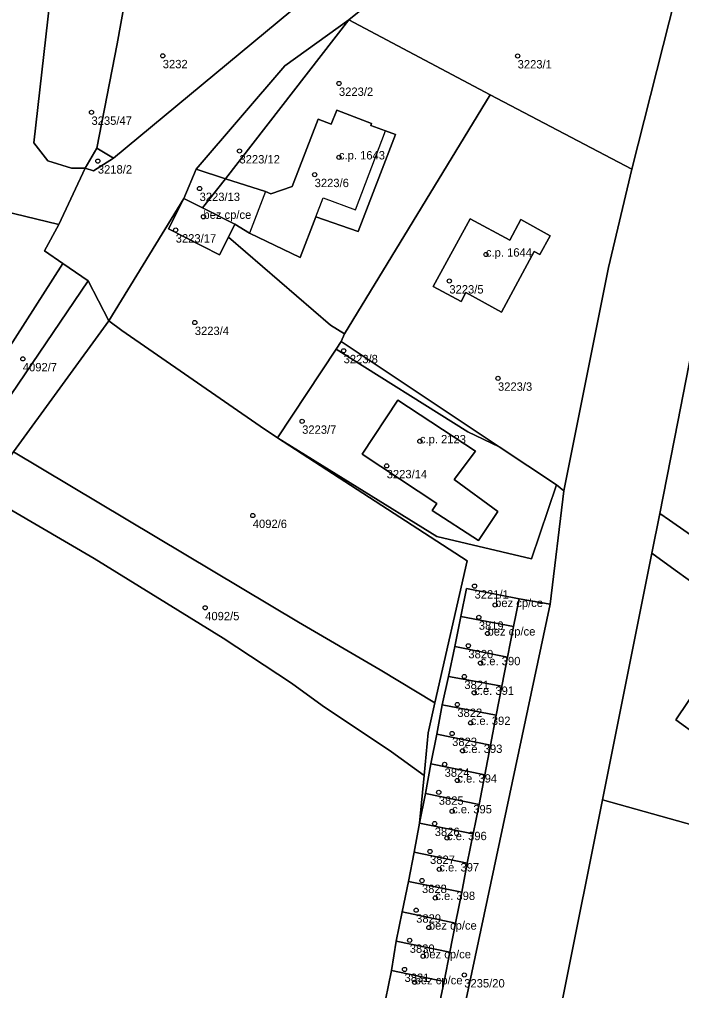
# Model space of a CAD drawing. Extents: x -878211 to -870363, y -1058464 to -1052522.
# Drawn here: x -875140.3 to -875061.1, y -1056719.1 to -1056603.1 of the extents above; entities that cross this region are included whole.
import ezdxf

# ---------------------------------------------------------------- set-up
doc = ezdxf.new("R2010")
doc.units = 0
for name, color, linetype in [('Vrstva 50', 7, 'Continuous'), ('Vrstva 51', 7, 'Continuous'), ('Vrstva 52', 7, 'Continuous')]:
    doc.layers.add(name, color=color, linetype=linetype)

msp = doc.modelspace()

# ---------------------------------------------------------------- linework, layer by layer
at = {"layer": 'Vrstva 50'}
for centre in [(-875123.14, -1056607.45994), (-875080.72, -1056607.47994), (-875102.08, -1056610.75994), (-875131.66, -1056614.21994), (-875113.97, -1056618.82994), (-875130.9, -1056620.03994), (-875102.08, -1056619.58994), (-875104.98, -1056621.65994), (-875118.74, -1056623.31994), (-875118.28, -1056626.68994), (-875121.59, -1056628.27994), (-875084.51, -1056631.19994), (-875088.88, -1056634.36994), (-875119.31, -1056639.32994), (-875101.52, -1056642.69994), (-875139.87, -1056643.66994), (-875083.07, -1056645.98994), (-875106.48, -1056651.12994), (-875092.4, -1056653.50994), (-875096.37, -1056656.44994), (-875112.38, -1056662.38994), (-875085.87, -1056670.81994), (-875118.07, -1056673.40994), (-875083.41, -1056673.06994), (-875085.36, -1056674.53994), (-875084.32, -1056676.47994), (-875086.61, -1056677.94994), (-875085.15, -1056680.01994), (-875087.09, -1056681.61994), (-875085.91, -1056683.55994), (-875087.93, -1056684.95994), (-875086.33, -1056687.15994), (-875088.55, -1056688.42994), (-875087.3, -1056690.49994), (-875089.45, -1056692.10994), (-875087.93, -1056694.03994), (-875090.15, -1056695.44994), (-875088.55, -1056697.71994), (-875090.63, -1056699.18994), (-875089.17, -1056700.91994), (-875091.19, -1056702.51994), (-875090.08, -1056704.65994), (-875092.16, -1056705.99994), (-875090.56, -1056708.06994), (-875092.85, -1056709.53994), (-875091.33, -1056711.60994), (-875093.62, -1056713.13994), (-875092.02, -1056715.03994), (-875094.24, -1056716.61994), (-875087.1, -1056717.27994), (-875093.03, -1056718.14994)]:
    msp.add_circle(centre, 0.25, dxfattribs=at)
at = {"layer": 'Vrstva 51'}
for points in [[(-874975.13, -1056393.67), (-874980.45, -1056410.63), (-874983.57, -1056424.89), (-875001.65, -1056483.66), (-875005.15, -1056492.08), (-875032.55, -1056540.02), (-875035.19, -1056534.63), (-875039.79, -1056543.8), (-875051.68, -1056572.91), (-875052.45, -1056574.91), (-875061.84, -1056600.38), (-875067.07, -1056621.01), (-875069.87, -1056632.77), (-875075.2, -1056659.42), (-875076.83, -1056672.97), (-875088.05, -1056725.8)], [(-875147.44, -1056651.53), (-875135.09, -1056632.27), (-875137.28, -1056630.77), (-875135.57, -1056627.63), (-875150.54, -1056623.98)], [(-875079.85, -1056742.65), (-875070.58, -1056696.36), (-875064.69, -1056666.87), (-875063.74, -1056662.13), (-875061.56, -1056651.21), (-875058, -1056632.84)], [(-875096.5, -1056720.24), (-875095.8, -1056716.75), (-875095.25, -1056713.24), (-875094.52, -1056709.74), (-875093.77, -1056706.12), (-875093.1, -1056702.61), (-875092.44, -1056699.14), (-875091.91, -1056693.44), (-875095.8, -1056690.63), (-875104.09, -1056685.1), (-875107.77, -1056682.42), (-875115.91, -1056677.03), (-875131.33, -1056667.53), (-875144.62, -1056659.79)], [(-875052, -1056670.3), (-875062.58, -1056662.94), (-875063.74, -1056662.13), (-875064.69, -1056666.87), (-875061.87, -1056668.91), (-875054.13, -1056674.49)], [(-875088.05, -1056725.8), (-875076.83, -1056672.97), (-875080.52, -1056672.32), (-875081.22, -1056675.66), (-875081.93, -1056679.3), (-875082.61, -1056682.78), (-875083.27, -1056686.24), (-875083.97, -1056689.81), (-875084.65, -1056693.35), (-875085.31, -1056696.89), (-875086.03, -1056700.41), (-875086.74, -1056703.92), (-875087.41, -1056707.4), (-875088.16, -1056711.08), (-875088.82, -1056714.54), (-875089.5, -1056718.06), (-875090.24, -1056721.62)]]:
    msp.add_lwpolyline(points, dxfattribs=at)
for points in [[(-875132.07, -1056634.34), (-875129.58, -1056639.14), (-875120.62, -1056624.51), (-875119.16, -1056621.01), (-875108.56, -1056608.67), (-875100.9, -1056603.18), (-875092.92, -1056596.72), (-875079.96, -1056589.72), (-875078.48, -1056587.09), (-875068.77, -1056576.4), (-875069.25, -1056570.23), (-875083.66, -1056582.09), (-875092.7, -1056589.53), (-875129.03, -1056619.67), (-875131.42, -1056621.2), (-875132.43, -1056620.89), (-875135.57, -1056627.63), (-875137.28, -1056630.77), (-875135.09, -1056632.27)], [(-875092.7, -1056589.53), (-875105.74, -1056586.1), (-875107.74, -1056599.08), (-875118.83, -1056597.36), (-875117.58, -1056589.47), (-875125.11, -1056588.01), (-875127.7, -1056601.16), (-875128.61, -1056606.02), (-875131.01, -1056618.5), (-875129.03, -1056619.67)], [(-875092.92, -1056596.72), (-875100.9, -1056603.18), (-875084.01, -1056612.14), (-875067.07, -1056621.01), (-875061.84, -1056600.38), (-875072.18, -1056596.84), (-875070.92, -1056593.21), (-875074.27, -1056592.01), (-875079.61, -1056589.86), (-875079.96, -1056589.72)], [(-875136.63, -1056600.96), (-875236.32, -1056602.29), (-875236.35, -1056608.98), (-875235.7, -1056613.74), (-875221.55, -1056617.25), (-875208.62, -1056621), (-875196.21, -1056625.52), (-875183.08, -1056631.34), (-875173.25, -1056636.71), (-875161.79, -1056643.58), (-875150.54, -1056623.98), (-875135.57, -1056627.63), (-875132.43, -1056620.89), (-875134.07, -1056620.89), (-875136.87, -1056620), (-875138.55, -1056617.84)], [(-875138.55, -1056617.84), (-875136.87, -1056620), (-875134.07, -1056620.89), (-875132.43, -1056620.89), (-875131.01, -1056618.5), (-875128.61, -1056606.02), (-875127.7, -1056601.16), (-875136.63, -1056600.96)], [(-875115.66, -1056622.14), (-875100.9, -1056603.18), (-875108.56, -1056608.67), (-875119.16, -1056621.01)], [(-875114.51, -1056627.56), (-875115.29, -1056629.12), (-875103.09, -1056639.66), (-875101.43, -1056640.66), (-875084.01, -1056612.14), (-875100.9, -1056603.18), (-875115.66, -1056622.14), (-875110.84, -1056623.69), (-875110.23, -1056623.95), (-875107.67, -1056623.06), (-875104.57, -1056615.01), (-875103.02, -1056615.62), (-875102.34, -1056613.94), (-875098.17, -1056615.55), (-875098.25, -1056615.79), (-875096.51, -1056616.44), (-875095.33, -1056616.86), (-875099.8, -1056628.45), (-875104.85, -1056626.68), (-875106.72, -1056631.55), (-875112.76, -1056628.63)], [(-875076.07, -1056658.7), (-875075.2, -1056659.42), (-875069.87, -1056632.77), (-875067.07, -1056621.01), (-875084.01, -1056612.14), (-875101.43, -1056640.66), (-875101.81, -1056641.6), (-875082.94, -1056654.17)], [(-875118.38, -1056625.63), (-875114.51, -1056627.56), (-875112.76, -1056628.63), (-875106.72, -1056631.55), (-875104.85, -1056626.68), (-875099.8, -1056628.45), (-875095.33, -1056616.86), (-875096.51, -1056616.44), (-875098.25, -1056615.79), (-875098.17, -1056615.55), (-875102.34, -1056613.94), (-875103.02, -1056615.62), (-875104.57, -1056615.01), (-875107.67, -1056623.06), (-875110.23, -1056623.95), (-875110.84, -1056623.69), (-875115.66, -1056622.14)], [(-875132.43, -1056620.89), (-875131.42, -1056621.2), (-875129.03, -1056619.67), (-875131.01, -1056618.5)], [(-875120.62, -1056624.51), (-875118.38, -1056625.63), (-875115.66, -1056622.14), (-875119.16, -1056621.01)], [(-875128.02, -1056640.29), (-875111.51, -1056651.71), (-875109.41, -1056653.11), (-875102.41, -1056642.51), (-875101.81, -1056641.6), (-875101.43, -1056640.66), (-875103.09, -1056639.66), (-875115.29, -1056629.12), (-875116.34, -1056631.22), (-875122.46, -1056628.14), (-875120.62, -1056624.51), (-875129.58, -1056639.14)], [(-875120.62, -1056624.51), (-875122.46, -1056628.14), (-875116.34, -1056631.22), (-875115.29, -1056629.12), (-875114.51, -1056627.56), (-875118.38, -1056625.63)], [(-875087.48, -1056636.81), (-875086.9, -1056635.74), (-875082.66, -1056638.07), (-875078.75, -1056630.82), (-875078.05, -1056631.2), (-875076.84, -1056628.96), (-875080.32, -1056627.03), (-875081.64, -1056629.5), (-875086.4, -1056626.95), (-875090.81, -1056635.01)], [(-875087.48, -1056636.81), (-875090.81, -1056635.01), (-875086.4, -1056626.95), (-875081.64, -1056629.5), (-875080.32, -1056627.03), (-875076.84, -1056628.96), (-875078.05, -1056631.2), (-875078.75, -1056630.82), (-875082.66, -1056638.07), (-875086.9, -1056635.74)], [(-875147.44, -1056651.53), (-875144.63, -1056652.87), (-875132.07, -1056634.34), (-875135.09, -1056632.27)], [(-875054.2, -1056635.62), (-875058, -1056632.84), (-875061.56, -1056651.21), (-875063.74, -1056662.13), (-875062.58, -1056662.94), (-875052, -1056670.3), (-875031.7, -1056677.75), (-874994.36, -1056690.62), (-874969.93, -1056695.59), (-874964.18, -1056690.59), (-874960.32, -1056681.28), (-874969.59, -1056675.5), (-874970.83, -1056674.71), (-874976.58, -1056671.11), (-874979.49, -1056669.39), (-874981.46, -1056668.14), (-875047.89, -1056640.23)], [(-875158.29, -1056678.56), (-875144.62, -1056659.79), (-875140.97, -1056654.78), (-875129.58, -1056639.14), (-875132.07, -1056634.34), (-875144.63, -1056652.87), (-875148.03, -1056657.88), (-875152.95, -1056665.14)], [(-875090.61, -1056684.77), (-875086.74, -1056667.79), (-875109.41, -1056653.11), (-875111.51, -1056651.71), (-875128.02, -1056640.29), (-875129.58, -1056639.14), (-875140.97, -1056654.78), (-875106.91, -1056675.12), (-875097.17, -1056680.82)], [(-875082.94, -1056654.17), (-875101.81, -1056641.6), (-875102.41, -1056642.51), (-875086.67, -1056652.4)], [(-875086.67, -1056652.4), (-875102.41, -1056642.51), (-875109.41, -1056653.11), (-875090.39, -1056664.91), (-875079.06, -1056667.56), (-875076.07, -1056658.7), (-875082.94, -1056654.17)], [(-875090.93, -1056661.77), (-875085.38, -1056665.36), (-875083.1, -1056661.9), (-875088.29, -1056658.09), (-875085.76, -1056654.68), (-875095.06, -1056648.6), (-875099.29, -1056655.07), (-875090.38, -1056660.94)], [(-875090.93, -1056661.77), (-875090.38, -1056660.94), (-875099.29, -1056655.07), (-875095.06, -1056648.6), (-875085.76, -1056654.68), (-875088.29, -1056658.09), (-875083.1, -1056661.9), (-875085.38, -1056665.36)], [(-875091.91, -1056693.44), (-875092.44, -1056699.14), (-875091.75, -1056695.59), (-875091.11, -1056692.06), (-875090.36, -1056688.49), (-875089.73, -1056685.01), (-875088.99, -1056681.62), (-875088.24, -1056678.03), (-875087.51, -1056674.45), (-875086.83, -1056671.12), (-875080.52, -1056672.32), (-875076.83, -1056672.97), (-875075.2, -1056659.42), (-875076.07, -1056658.7), (-875079.06, -1056667.56), (-875090.39, -1056664.91), (-875109.41, -1056653.11), (-875086.74, -1056667.79), (-875090.61, -1056684.77), (-875091.43, -1056688.36)], [(-875090.61, -1056684.77), (-875097.17, -1056680.82), (-875106.91, -1056675.12), (-875140.97, -1056654.78), (-875144.62, -1056659.79), (-875131.33, -1056667.53), (-875115.91, -1056677.03), (-875107.77, -1056682.42), (-875104.09, -1056685.1), (-875095.8, -1056690.63), (-875091.91, -1056693.44), (-875091.43, -1056688.36)], [(-875033.98, -1056681.51), (-875054.13, -1056674.49), (-875061.87, -1056668.91), (-875064.69, -1056666.87), (-875070.58, -1056696.36), (-874971.25, -1056724.17), (-874965.51, -1056725.78), (-874958.57, -1056727.67), (-874952.5, -1056725.13), (-874945.84, -1056719.49), (-874939.85, -1056712.99), (-874937.64, -1056707.11), (-874938.78, -1056706.6), (-874939.54, -1056709.59), (-874960.23, -1056695.82), (-874961.04, -1056695.28), (-874963.53, -1056701.5), (-874995.69, -1056695.3)], [(-875081.22, -1056675.66), (-875080.52, -1056672.32), (-875086.83, -1056671.12), (-875087.51, -1056674.45)], [(-875088.24, -1056678.03), (-875081.93, -1056679.3), (-875081.22, -1056675.66), (-875087.51, -1056674.45)], [(-875082.61, -1056682.78), (-875081.93, -1056679.3), (-875088.24, -1056678.03), (-875088.99, -1056681.62)], [(-875039.56, -1056689.55), (-875045.19, -1056698.06), (-875048.14, -1056696.15), (-875048.31, -1056696.37), (-875059.07, -1056689.09), (-875059.04, -1056688.8), (-875061.81, -1056686.81), (-875056.14, -1056678.39), (-875048.06, -1056683.83), (-875046.64, -1056681.74), (-875044.88, -1056682.91), (-875046.32, -1056685)], [(-875039.56, -1056689.55), (-875046.32, -1056685), (-875044.88, -1056682.91), (-875046.64, -1056681.74), (-875048.06, -1056683.83), (-875056.14, -1056678.39), (-875061.81, -1056686.81), (-875059.04, -1056688.8), (-875059.07, -1056689.09), (-875048.31, -1056696.37), (-875048.14, -1056696.15), (-875045.19, -1056698.06)], [(-875083.27, -1056686.24), (-875082.61, -1056682.78), (-875088.99, -1056681.62), (-875089.73, -1056685.01)], [(-875090.36, -1056688.49), (-875083.97, -1056689.81), (-875083.27, -1056686.24), (-875089.73, -1056685.01)], [(-875084.65, -1056693.35), (-875083.97, -1056689.81), (-875090.36, -1056688.49), (-875091.11, -1056692.06)], [(-875091.75, -1056695.59), (-875085.31, -1056696.89), (-875084.65, -1056693.35), (-875091.11, -1056692.06)], [(-875086.62, -1056776.65), (-875097.04, -1056808.99), (-875096.89, -1056816.97), (-875060.2, -1056830.88), (-875017.6, -1056842.12), (-874988.92, -1056847.01), (-874988.71, -1056845.15), (-874986.17, -1056827.14), (-874985.74, -1056823.88), (-874982.68, -1056800.77), (-874979, -1056778.71), (-874977.65, -1056766.28), (-874974.89, -1056749.21), (-874974.26, -1056745.05), (-874971.25, -1056724.17), (-875070.58, -1056696.36), (-875079.85, -1056742.65), (-875077.16, -1056744.23)], [(-875086.03, -1056700.41), (-875085.31, -1056696.89), (-875091.75, -1056695.59), (-875092.44, -1056699.14)], [(-875092.44, -1056699.14), (-875093.1, -1056702.61), (-875086.74, -1056703.92), (-875086.03, -1056700.41)], [(-875093.77, -1056706.12), (-875087.41, -1056707.4), (-875086.74, -1056703.92), (-875093.1, -1056702.61)], [(-875093.77, -1056706.12), (-875094.52, -1056709.74), (-875088.16, -1056711.08), (-875087.41, -1056707.4)], [(-875095.25, -1056713.24), (-875088.82, -1056714.54), (-875088.16, -1056711.08), (-875094.52, -1056709.74)], [(-875095.25, -1056713.24), (-875095.8, -1056716.75), (-875089.5, -1056718.06), (-875088.82, -1056714.54)], [(-875096.5, -1056720.24), (-875090.24, -1056721.62), (-875089.5, -1056718.06), (-875095.8, -1056716.75)]]:
    msp.add_lwpolyline(points, close=True, dxfattribs=at)
at = {"layer": 'Vrstva 52'}
for points in [[(-875098.17, -1056615.55), (-875102.34, -1056613.94), (-875103.02, -1056615.62), (-875104.57, -1056615.01), (-875107.67, -1056623.06), (-875110.23, -1056623.95), (-875110.84, -1056623.69), (-875112.76, -1056628.63), (-875106.72, -1056631.55), (-875104.85, -1056626.68), (-875103.98, -1056624.42), (-875100.12, -1056625.85), (-875096.51, -1056616.44), (-875098.25, -1056615.79)], [(-875120.62, -1056624.51), (-875122.46, -1056628.14), (-875116.34, -1056631.22), (-875115.29, -1056629.12), (-875114.51, -1056627.56), (-875118.38, -1056625.63)], [(-875086.4, -1056626.95), (-875090.81, -1056635.01), (-875087.48, -1056636.81), (-875086.9, -1056635.74), (-875082.66, -1056638.07), (-875078.75, -1056630.82), (-875078.05, -1056631.2), (-875076.84, -1056628.96), (-875080.32, -1056627.03), (-875081.64, -1056629.5)], [(-875095.06, -1056648.6), (-875099.29, -1056655.07), (-875090.38, -1056660.94), (-875090.93, -1056661.77), (-875085.38, -1056665.36), (-875083.1, -1056661.9), (-875088.29, -1056658.09), (-875085.76, -1056654.68)], [(-875086.83, -1056671.12), (-875087.51, -1056674.45), (-875081.22, -1056675.66), (-875080.52, -1056672.32)], [(-875088.24, -1056678.03), (-875081.93, -1056679.3), (-875081.22, -1056675.66), (-875087.51, -1056674.45)], [(-875088.99, -1056681.62), (-875082.61, -1056682.78), (-875081.93, -1056679.3), (-875088.24, -1056678.03)], [(-875046.32, -1056685), (-875044.88, -1056682.91), (-875046.64, -1056681.74), (-875048.06, -1056683.83), (-875056.14, -1056678.39), (-875061.81, -1056686.81), (-875059.04, -1056688.8), (-875059.07, -1056689.09), (-875048.31, -1056696.37), (-875048.14, -1056696.15), (-875045.19, -1056698.06), (-875039.56, -1056689.55)], [(-875088.99, -1056681.62), (-875089.73, -1056685.01), (-875083.27, -1056686.24), (-875082.61, -1056682.78)], [(-875090.36, -1056688.49), (-875083.97, -1056689.81), (-875083.27, -1056686.24), (-875089.73, -1056685.01)], [(-875084.65, -1056693.35), (-875083.97, -1056689.81), (-875090.36, -1056688.49), (-875091.11, -1056692.06)], [(-875091.75, -1056695.59), (-875085.31, -1056696.89), (-875084.65, -1056693.35), (-875091.11, -1056692.06)], [(-875091.75, -1056695.59), (-875092.44, -1056699.14), (-875086.03, -1056700.41), (-875085.31, -1056696.89)], [(-875093.1, -1056702.61), (-875086.74, -1056703.92), (-875086.03, -1056700.41), (-875092.44, -1056699.14)], [(-875093.1, -1056702.61), (-875093.77, -1056706.12), (-875087.41, -1056707.4), (-875086.74, -1056703.92)], [(-875094.52, -1056709.74), (-875088.16, -1056711.08), (-875087.41, -1056707.4), (-875093.77, -1056706.12)], [(-875094.52, -1056709.74), (-875095.25, -1056713.24), (-875088.82, -1056714.54), (-875088.16, -1056711.08)], [(-875095.8, -1056716.75), (-875089.5, -1056718.06), (-875088.82, -1056714.54), (-875095.25, -1056713.24)], [(-875095.8, -1056716.75), (-875096.5, -1056720.24), (-875090.24, -1056721.62), (-875089.5, -1056718.06)]]:
    msp.add_lwpolyline(points, close=True, dxfattribs=at)

# ---------------------------------------------------------------- texts
at = {"layer": 'Vrstva 50'}
for s, p in [('3232', (-875123.14, -1056608.949)), ('3223/1', (-875080.72, -1056608.969)), ('3223/2', (-875102.08, -1056612.249)), ('3235/47', (-875131.66, -1056615.709)), ('3223/12', (-875113.97, -1056620.319)), ('c.p. 1643', (-875102.08, -1056619.84)), ('3218/2', (-875130.9, -1056621.529)), ('3223/6', (-875104.98, -1056623.149)), ('3223/13', (-875118.74, -1056624.809)), ('bez cp/ce', (-875118.28, -1056626.94)), ('3223/17', (-875121.59, -1056629.769)), ('c.p. 1644', (-875084.51, -1056631.45)), ('3223/5', (-875088.88, -1056635.859)), ('3223/4', (-875119.31, -1056640.819)), ('3223/8', (-875101.52, -1056644.189)), ('4092/7', (-875139.87, -1056645.159)), ('3223/3', (-875083.07, -1056647.479)), ('3223/7', (-875106.48, -1056652.619)), ('c.p. 2123', (-875092.4, -1056653.76)), ('3223/14', (-875096.37, -1056657.939)), ('4092/6', (-875112.38, -1056663.879)), ('3221/1', (-875085.87, -1056672.309)), ('bez cp/ce', (-875083.41, -1056673.32)), ('4092/5', (-875118.07, -1056674.899)), ('3819', (-875085.36, -1056676.029)), ('bez cp/ce', (-875084.32, -1056676.73)), ('3820', (-875086.61, -1056679.439)), ('c.e. 390', (-875085.15, -1056680.27)), ('3821', (-875087.09, -1056683.109)), ('c.e. 391', (-875085.91, -1056683.81)), ('3822', (-875087.93, -1056686.449)), ('c.e. 392', (-875086.33, -1056687.409)), ('3823', (-875088.55, -1056689.919)), ('c.e. 393', (-875087.3, -1056690.75)), ('3824', (-875089.45, -1056693.599)), ('c.e. 394', (-875087.93, -1056694.29)), ('3825', (-875090.15, -1056696.939)), ('c.e. 395', (-875088.55, -1056697.97)), ('3826', (-875090.63, -1056700.679)), ('c.e. 396', (-875089.17, -1056701.169)), ('3827', (-875091.19, -1056704.009)), ('c.e. 397', (-875090.08, -1056704.909)), ('3828', (-875092.16, -1056707.489)), ('c.e. 398', (-875090.56, -1056708.32)), ('3829', (-875092.85, -1056711.029)), ('bez cp/ce', (-875091.33, -1056711.86)), ('3830', (-875093.62, -1056714.629)), ('bez cp/ce', (-875092.02, -1056715.29)), ('3831', (-875094.24, -1056718.109)), ('bez cp/ce', (-875093.03, -1056718.399)), ('3235/20', (-875087.1, -1056718.769))]:
    msp.add_text(s, height=0.999996, dxfattribs=at).set_placement(p)

doc.saveas('drawing.dxf')
